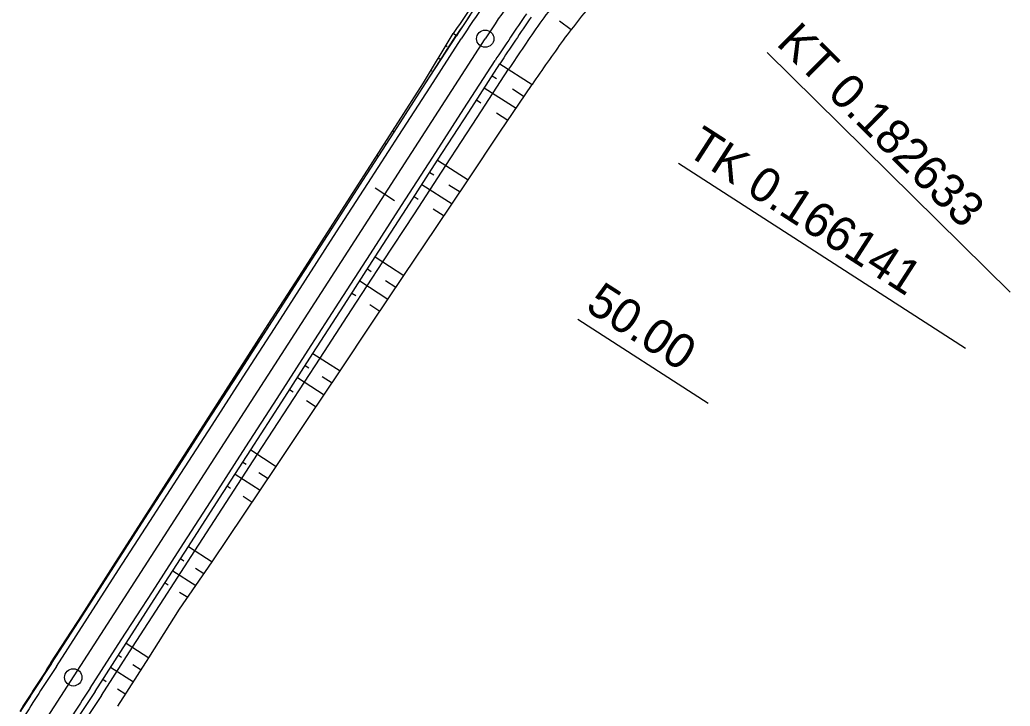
# Model space of a CAD drawing. Extents: x -481645 to -478728, y -1113199 to -1110710.
# Drawn here: x -479835 to -479748.9, y -1111705.7 to -1111646 of the extents above; entities that cross this region are included whole.
import ezdxf

# ---------------------------------------------------------------- set-up
doc = ezdxf.new("R2010")
doc.units = 0
for name, color, linetype in [('CP14_HATCH_SLOPE_L', 7, 'Continuous'), ('CP1_HECTOMETRY', 7, 'Continuous'), ('O6_HATCH_SLOPE_L', 7, 'Continuous'), ('O6_HATCH_SLOPE_R', 7, 'Continuous'), ('O6_HECTOMETRY', 7, 'Continuous'), ('O6_HLBODY', 7, 'Continuous'), ('O6_HRANA_TELESO', 7, 'Continuous'), ('O6_OSA', 7, 'Continuous'), ('O6_VOZOVKA', 7, 'Continuous'), ('O6_ZPEVKRAJ', 7, 'Continuous')]:
    doc.layers.add(name, color=color, linetype=linetype)

msp = doc.modelspace()

# ---------------------------------------------------------------- linework, layer by layer
at = {"layer": 'CP14_HATCH_SLOPE_L'}
for p, q in [((-479788.058, -1111646.063), (-479787.044, -1111646.813)), ((-479793.261, -1111649.803), (-479790.46, -1111651.609)), ((-479793.939, -1111650.854), (-479793.564, -1111651.096)), ((-479794.616, -1111651.905), (-479791.855, -1111653.684)), ((-479792.173, -1111651.992), (-479791.158, -1111652.647)), ((-479795.293, -1111652.955), (-479794.923, -1111653.194)), ((-479793.553, -1111654.077), (-479792.553, -1111654.722)), ((-479798.68, -1111658.208), (-479796.031, -1111659.916)), ((-479799.357, -1111659.259), (-479799.003, -1111659.487)), ((-479800.035, -1111660.309), (-479797.424, -1111661.992)), ((-479797.688, -1111660.334), (-479796.727, -1111660.954)), ((-479800.712, -1111661.36), (-479800.363, -1111661.585)), ((-479799.067, -1111662.42), (-479798.12, -1111663.031)), ((-479804.098, -1111666.613), (-479801.602, -1111668.222)), ((-479804.776, -1111667.663), (-479804.443, -1111667.878)), ((-479805.453, -1111668.714), (-479802.998, -1111670.297)), ((-479803.205, -1111668.676), (-479802.3, -1111669.26)), ((-479806.13, -1111669.765), (-479805.802, -1111669.976)), ((-479804.585, -1111670.76), (-479803.695, -1111671.334)), ((-479809.517, -1111675.017), (-479807.161, -1111676.536)), ((-479810.194, -1111676.068), (-479809.882, -1111676.269)), ((-479810.872, -1111677.119), (-479808.55, -1111678.615)), ((-479808.714, -1111677.023), (-479807.856, -1111677.576)), ((-479811.549, -1111678.169), (-479811.243, -1111678.366)), ((-479810.091, -1111679.11), (-479809.245, -1111679.655)), ((-479814.936, -1111683.422), (-479812.716, -1111684.853)), ((-479815.613, -1111684.473), (-479815.322, -1111684.66)), ((-479816.29, -1111685.523), (-479814.111, -1111686.928)), ((-479814.223, -1111685.37), (-479813.414, -1111685.891)), ((-479816.968, -1111686.574), (-479816.682, -1111686.758)), ((-479815.602, -1111687.454), (-479814.809, -1111687.966)), ((-479820.354, -1111691.827), (-479818.302, -1111693.15)), ((-479821.031, -1111692.877), (-479820.752, -1111693.058)), ((-479821.709, -1111693.928), (-479819.713, -1111695.215)), ((-479819.74, -1111693.71), (-479819.008, -1111694.182)), ((-479822.386, -1111694.979), (-479822.106, -1111695.16)), ((-479821.122, -1111695.794), (-479820.419, -1111696.247)), ((-479825.773, -1111700.232), (-479823.799, -1111701.504)), ((-479826.45, -1111701.282), (-479826.17, -1111701.462)), ((-479827.127, -1111702.333), (-479825.141, -1111703.614)), ((-479825.18, -1111702.101), (-479824.47, -1111702.559)), ((-479827.805, -1111703.383), (-479827.525, -1111703.564)), ((-479826.528, -1111704.206), (-479825.811, -1111704.668))]:
    msp.add_line(p, q, dxfattribs=at)
at = {"layer": 'CP1_HECTOMETRY'}
msp.add_line((-479832.606, -1111706.678), (-479794.534, -1111647.625), dxfattribs=at)
msp.add_arc((-479727.296, -1111690.973), 80, 135.37881, 147.1898, dxfattribs=at)
at = {"layer": 'O6_HATCH_SLOPE_L'}
msp.add_circle((-479830.373, -1111703.215), 0.75, dxfattribs=at)
at = {"layer": 'O6_HATCH_SLOPE_R'}
for p, q in [((-479797.043, -1111647.365), (-479797.321, -1111647.186)), ((-479797.849, -1111648.333), (-479797.969, -1111648.256)), ((-479797.721, -1111648.416), (-479797.725, -1111648.413)), ((-479798.398, -1111649.466), (-479798.617, -1111649.325)), ((-479799.174, -1111650.453), (-479799.264, -1111650.395)), ((-479799.075, -1111650.517), (-479799.08, -1111650.514)), ((-479802.462, -1111655.77), (-479802.59, -1111655.687)), ((-479803.207, -1111656.776), (-479803.266, -1111656.738)), ((-479803.139, -1111656.82), (-479803.144, -1111656.818)), ((-479803.817, -1111657.871), (-479803.943, -1111657.79)), ((-479804.561, -1111658.878), (-479804.619, -1111658.841)), ((-479804.494, -1111658.921), (-479804.498, -1111658.918)), ((-479807.881, -1111664.174), (-479808, -1111664.097)), ((-479808.621, -1111665.184), (-479808.676, -1111665.149)), ((-479808.558, -1111665.225), (-479808.562, -1111665.222)), ((-479809.235, -1111666.276), (-479809.352, -1111666.2)), ((-479809.974, -1111667.286), (-479810.028, -1111667.252)), ((-479809.913, -1111667.326), (-479809.917, -1111667.324)), ((-479813.299, -1111672.579), (-479813.404, -1111672.512)), ((-479814.032, -1111673.594), (-479814.079, -1111673.564)), ((-479813.976, -1111673.63), (-479813.98, -1111673.627)), ((-479814.654, -1111674.68), (-479814.754, -1111674.616)), ((-479815.384, -1111675.696), (-479815.429, -1111675.668)), ((-479815.331, -1111675.731), (-479815.336, -1111675.728)), ((-479818.718, -1111680.984), (-479818.804, -1111680.928)), ((-479819.442, -1111682.004), (-479819.481, -1111681.979)), ((-479819.395, -1111682.034), (-479819.399, -1111682.032)), ((-479820.072, -1111683.085), (-479820.158, -1111683.03)), ((-479820.796, -1111684.106), (-479820.835, -1111684.081)), ((-479820.75, -1111684.136), (-479820.754, -1111684.133)), ((-479824.136, -1111689.389), (-479824.219, -1111689.335)), ((-479824.857, -1111690.411), (-479824.892, -1111690.388)), ((-479824.814, -1111690.439), (-479824.818, -1111690.436)), ((-479825.491, -1111691.49), (-479825.565, -1111691.442)), ((-479826.208, -1111692.515), (-479826.238, -1111692.495)), ((-479826.168, -1111692.54), (-479826.172, -1111692.538)), ((-479829.555, -1111697.793), (-479829.612, -1111697.757)), ((-479830.264, -1111698.823), (-479830.288, -1111698.808)), ((-479830.232, -1111698.844), (-479830.236, -1111698.841)), ((-479830.91, -1111699.894), (-479830.965, -1111699.859)), ((-479831.618, -1111700.925), (-479831.641, -1111700.91)), ((-479831.587, -1111700.945), (-479831.591, -1111700.942))]:
    msp.add_line(p, q, dxfattribs=at)
at = {"layer": 'O6_HECTOMETRY'}
for p, q in [((-479770.002, -1111648.828), (-479748.863, -1111669.69)), ((-479777.724, -1111658.462), (-479752.762, -1111674.555))]:
    msp.add_line(p, q, dxfattribs=at)
msp.add_circle((-479794.534, -1111647.625), 0.75, dxfattribs=at)
at = {"layer": 'O6_HLBODY'}
for p, q in [((-479802.44, -1111661.733), (-479804.121, -1111660.649)), ((-479786.471, -1111672.028), (-479775.124, -1111679.343))]:
    msp.add_line(p, q, dxfattribs=at)
at = {"layer": 'O6_HRANA_TELESO'}
for p, q in [((-479799.761, -1111651.562), (-479797.052, -1111647.36)), ((-479795.236, -1111654.479), (-479792.505, -1111650.291)), ((-479802.47, -1111655.764), (-479799.761, -1111651.562)), ((-479797.966, -1111658.668), (-479795.236, -1111654.479)), ((-479805.18, -1111659.967), (-479802.47, -1111655.764)), ((-479800.697, -1111662.857), (-479797.966, -1111658.668)), ((-479807.889, -1111664.169), (-479805.18, -1111659.967)), ((-479803.428, -1111667.045), (-479800.697, -1111662.857)), ((-479810.598, -1111668.371), (-479807.889, -1111664.169)), ((-479806.158, -1111671.234), (-479803.428, -1111667.045)), ((-479813.308, -1111672.574), (-479810.598, -1111668.371)), ((-479808.889, -1111675.423), (-479806.158, -1111671.234)), ((-479816.017, -1111676.776), (-479813.308, -1111672.574)), ((-479811.619, -1111679.611), (-479808.889, -1111675.423)), ((-479818.726, -1111680.978), (-479816.017, -1111676.776)), ((-479814.35, -1111683.8), (-479811.619, -1111679.611)), ((-479821.435, -1111685.181), (-479818.726, -1111680.978)), ((-479817.076, -1111687.991), (-479814.35, -1111683.8)), ((-479824.145, -1111689.383), (-479821.435, -1111685.181)), ((-479819.796, -1111692.187), (-479817.076, -1111687.991)), ((-479826.854, -1111693.585), (-479824.145, -1111689.383)), ((-479822.503, -1111696.39), (-479819.796, -1111692.187)), ((-479829.563, -1111697.788), (-479826.854, -1111693.585)), ((-479825.213, -1111700.593), (-479822.503, -1111696.39)), ((-479832.273, -1111701.99), (-479829.563, -1111697.788)), ((-479827.922, -1111704.795), (-479825.213, -1111700.593))]:
    msp.add_line(p, q, dxfattribs=at)
for centre, radius, start, end in [((-479727.543, -1111691.295), 76.812, 140.54328, 144.12431), ((-479590.768, -1111782.812), 246.78, 145.52375, 146.70979), ((-479600.457, -1111777.713), 230.475, 145.23126, 146.43618), ((-479622.55, -1111840.131), 251.13, 146.62782, 147.7695), ((-479620.373, -1111841.53), 248.542, 146.62285, 147.77432)]:
    msp.add_arc(centre, radius, start, end, dxfattribs=at)
at = {"layer": 'O6_OSA'}
for p, q in [((-479799.912, -1111651.465), (-479797.321, -1111647.186)), ((-479802.59, -1111655.687), (-479799.912, -1111651.465)), ((-479793.25, -1111655.76), (-479790.46, -1111651.609)), ((-479805.295, -1111659.892), (-479802.59, -1111655.687)), ((-479796.031, -1111659.916), (-479793.25, -1111655.76)), ((-479808, -1111664.097), (-479805.295, -1111659.892)), ((-479798.816, -1111664.069), (-479796.031, -1111659.916)), ((-479801.602, -1111668.222), (-479798.816, -1111664.069)), ((-479810.704, -1111668.303), (-479808, -1111664.097)), ((-479813.404, -1111672.512), (-479810.704, -1111668.303)), ((-479804.393, -1111672.372), (-479801.602, -1111668.222)), ((-479816.104, -1111676.72), (-479813.404, -1111672.512)), ((-479807.161, -1111676.536), (-479804.393, -1111672.372)), ((-479818.804, -1111680.928), (-479816.104, -1111676.72)), ((-479809.939, -1111680.694), (-479807.161, -1111676.536)), ((-479821.512, -1111685.131), (-479818.804, -1111680.928)), ((-479812.716, -1111684.853), (-479809.939, -1111680.694)), ((-479824.219, -1111689.335), (-479821.512, -1111685.131)), ((-479815.506, -1111689.003), (-479812.716, -1111684.853)), ((-479818.302, -1111693.15), (-479815.506, -1111689.003)), ((-479826.911, -1111693.548), (-479824.219, -1111689.335)), ((-479821.124, -1111697.28), (-479818.302, -1111693.15)), ((-479829.612, -1111697.757), (-479826.911, -1111693.548)), ((-479823.799, -1111701.504), (-479821.124, -1111697.28)), ((-479832.318, -1111701.961), (-479829.612, -1111697.757)), ((-479826.482, -1111705.723), (-479823.799, -1111701.504))]:
    msp.add_line(p, q, dxfattribs=at)
for centre, radius, start, end in [((-479591.773, -1111785.199), 247.584, 144.93568, 146.12116), ((-479728.156, -1111692.078), 74.274, 139.76559, 143.34721), ((-479606.606, -1111777.73), 222.954, 144.33538, 145.55048), ((-479622.428, -1111839.891), 251.154, 146.68899, 147.83058)]:
    msp.add_arc(centre, radius, start, end, dxfattribs=at)
at = {"layer": 'O6_VOZOVKA'}
for p, q in [((-479799.332, -1111651.838), (-479796.623, -1111647.636)), ((-479796.391, -1111653.735), (-479793.682, -1111649.532)), ((-479802.042, -1111656.041), (-479799.332, -1111651.838)), ((-479799.1, -1111657.937), (-479796.391, -1111653.735)), ((-479804.751, -1111660.243), (-479802.042, -1111656.041)), ((-479801.809, -1111662.139), (-479799.1, -1111657.937)), ((-479807.46, -1111664.445), (-479804.751, -1111660.243)), ((-479804.519, -1111666.342), (-479801.809, -1111662.139)), ((-479810.17, -1111668.648), (-479807.46, -1111664.445)), ((-479807.228, -1111670.544), (-479804.519, -1111666.342)), ((-479812.879, -1111672.85), (-479810.17, -1111668.648)), ((-479809.937, -1111674.747), (-479807.228, -1111670.544)), ((-479815.588, -1111677.052), (-479812.879, -1111672.85)), ((-479812.647, -1111678.949), (-479809.937, -1111674.747)), ((-479818.297, -1111681.255), (-479815.588, -1111677.052)), ((-479815.356, -1111683.151), (-479812.647, -1111678.949)), ((-479821.007, -1111685.457), (-479818.297, -1111681.255)), ((-479818.065, -1111687.354), (-479815.356, -1111683.151)), ((-479823.716, -1111689.659), (-479821.007, -1111685.457)), ((-479820.774, -1111691.556), (-479818.065, -1111687.354)), ((-479826.425, -1111693.862), (-479823.716, -1111689.659)), ((-479823.484, -1111695.758), (-479820.774, -1111691.556)), ((-479829.135, -1111698.064), (-479826.425, -1111693.862)), ((-479826.193, -1111699.961), (-479823.484, -1111695.758)), ((-479831.844, -1111702.266), (-479829.135, -1111698.064)), ((-479828.902, -1111704.163), (-479826.193, -1111699.961))]:
    msp.add_line(p, q, dxfattribs=at)
for centre, radius, start, end in [((-479591.613, -1111782.24), 245.25, 145.52441, 146.71211), ((-479597.411, -1111778.317), 234.75, 145.5291, 146.72872), ((-479622.336, -1111840.268), 250.875, 146.62733, 147.76997), ((-479620.863, -1111841.214), 249.125, 146.62398, 147.77323)]:
    msp.add_arc(centre, radius, start, end, dxfattribs=at)
at = {"layer": 'O6_ZPEVKRAJ'}
for p, q in [((-479799.753, -1111651.567), (-479797.043, -1111647.365)), ((-479795.971, -1111654.006), (-479793.261, -1111649.803)), ((-479802.462, -1111655.77), (-479799.753, -1111651.567)), ((-479798.68, -1111658.208), (-479795.971, -1111654.006)), ((-479805.171, -1111659.972), (-479802.462, -1111655.77)), ((-479801.389, -1111662.41), (-479798.68, -1111658.208)), ((-479807.881, -1111664.174), (-479805.171, -1111659.972)), ((-479804.098, -1111666.613), (-479801.389, -1111662.41)), ((-479810.59, -1111668.377), (-479807.881, -1111664.174)), ((-479806.808, -1111670.815), (-479804.098, -1111666.613)), ((-479813.299, -1111672.579), (-479810.59, -1111668.377)), ((-479809.517, -1111675.017), (-479806.808, -1111670.815)), ((-479816.008, -1111676.781), (-479813.299, -1111672.579)), ((-479812.226, -1111679.22), (-479809.517, -1111675.017)), ((-479818.718, -1111680.984), (-479816.008, -1111676.781)), ((-479814.936, -1111683.422), (-479812.226, -1111679.22)), ((-479821.427, -1111685.186), (-479818.718, -1111680.984)), ((-479817.645, -1111687.625), (-479814.936, -1111683.422)), ((-479824.136, -1111689.389), (-479821.427, -1111685.186)), ((-479820.354, -1111691.827), (-479817.645, -1111687.625)), ((-479826.846, -1111693.591), (-479824.136, -1111689.389)), ((-479823.063, -1111696.029), (-479820.354, -1111691.827)), ((-479829.555, -1111697.793), (-479826.846, -1111693.591)), ((-479825.773, -1111700.232), (-479823.063, -1111696.029)), ((-479832.264, -1111701.996), (-479829.555, -1111697.793)), ((-479828.482, -1111704.434), (-479825.773, -1111700.232))]:
    msp.add_line(p, q, dxfattribs=at)
for centre, radius, start, end in [((-479590.785, -1111782.801), 246.75, 145.52376, 146.70984), ((-479598.239, -1111777.757), 233.25, 145.52979, 146.7312), ((-479622.546, -1111840.133), 251.125, 146.62781, 147.76951), ((-479620.653, -1111841.35), 248.875, 146.62349, 147.7737)]:
    msp.add_arc(centre, radius, start, end, dxfattribs=at)

# ---------------------------------------------------------------- texts
at = {"layer": 'O6_HECTOMETRY'}
for s, rotation, p in [('KT 0.182633', 315.37882, (-479769.3, -1111648.116)), ('TK 0.166141', 327.1898, (-479777.183, -1111657.621))]:
    msp.add_text(s, height=3, rotation=rotation, dxfattribs=at).set_placement(p)
at = {"layer": 'O6_HLBODY'}
msp.add_text('50.00', height=3, rotation=327.1898, dxfattribs=at).set_placement((-479785.93, -1111671.187))

doc.saveas('drawing.dxf')
